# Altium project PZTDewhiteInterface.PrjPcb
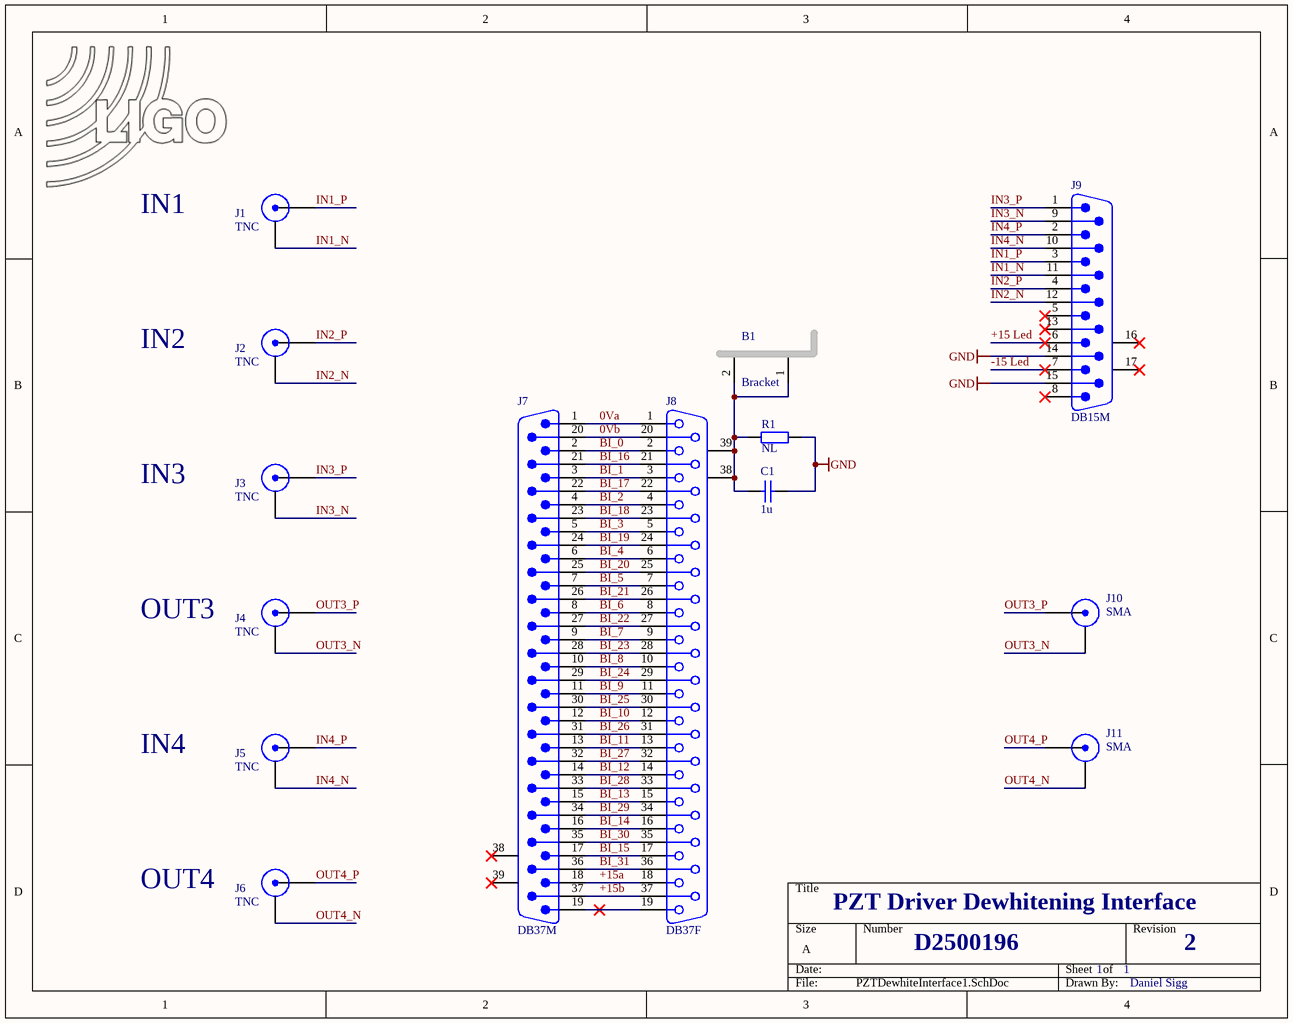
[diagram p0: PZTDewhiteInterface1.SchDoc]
REV: 2; DCC: D2500196
1 sheet, 15 parts. Net scope: global (net labels, ports and power ports of the same name join across sheets).
Board file: PZTDewhiteInterface.PcbDoc

## Sheet PZTDewhiteInterface1.SchDoc
size A; DocumentNumber: D2500196; Revision: 2; SheetNumber: 1; SheetTotal: 1

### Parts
B1  Bracket  [Bracket-RA_708]
C1  1u  [CC2013-0805]
J1  TNC  [TNC2]
J2  TNC  [TNC2]
J3  TNC  [TNC2]
J4  TNC  [TNC2]
J5  TNC  [TNC2]
J6  TNC  [TNC2]
J7  DB37M  [DB37M-RA]
J8  DB37F  [DB37F-RA]
J9  DB15M  [DB15M-RA]
J10  SMA  [SMA]
J11  SMA  [SMA]
LOGO1  LIGO logo  [LIGO_LOGO]  (value not drawn)  (no BOM)
R1  NL  [CR2012-0805]

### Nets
GND: C1.2 J9.14 J9.15 R1.2
0Va: J7.1 J8.1
0Vb: J7.20 J8.20
+15 Led: J9.6
+15a: J7.18 J8.18
+15b: J7.37 J8.37
-15 Led: J9.7
BI_0: J7.2 J8.2
BI_1: J7.3 J8.3
BI_2: J7.4 J8.4
BI_3: J7.5 J8.5
BI_4: J7.6 J8.6
BI_5: J7.7 J8.7
BI_6: J7.8 J8.8
BI_7: J7.9 J8.9
BI_8: J7.10 J8.10
BI_9: J7.11 J8.11
BI_10: J7.12 J8.12
BI_11: J7.13 J8.13
BI_12: J7.14 J8.14
BI_13: J7.15 J8.15
BI_14: J7.16 J8.16
BI_15: J7.17 J8.17
BI_16: J7.21 J8.21
BI_17: J7.22 J8.22
BI_18: J7.23 J8.23
BI_19: J7.24 J8.24
BI_20: J7.25 J8.25
BI_21: J7.26 J8.26
BI_22: J7.27 J8.27
BI_23: J7.28 J8.28
BI_24: J7.29 J8.29
BI_25: J7.30 J8.30
BI_26: J7.31 J8.31
BI_27: J7.32 J8.32
BI_28: J7.33 J8.33
BI_29: J7.34 J8.34
BI_30: J7.35 J8.35
BI_31: J7.36 J8.36
IN1_N: J1.2(Y) J9.11
IN1_P: J1.1(X) J9.3
IN2_N: J2.2(Y) J9.12
IN2_P: J2.1(X) J9.4
IN3_N: J3.2(Y) J9.9
IN3_P: J3.1(X) J9.1
IN4_N: J5.2(Y) J9.10
IN4_P: J5.1(X) J9.2
OUT3_N: J4.2(Y) J10.2(Y)
OUT3_P: J4.1(X) J10.1(X)
OUT4_N: J6.2(Y) J11.2(Y)
OUT4_P: J6.1(X) J11.1(X)
NetB1_1: B1.1(GND) B1.2(GND) C1.1 J8.38 J8.39 R1.1
NetJ7_19: J7.19 J8.19

Not connected (* = marked no-connect by the designer): J7 38* 39*; J9 5* 8* 13* 16(MH1)* 17(MH2)*

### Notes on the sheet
- IN1
- IN2
- IN3
- OUT3
- IN4
- OUT4
- PZT Driver Dewhitening Interface
- Daniel Sigg

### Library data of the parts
B1 = Bracket_708: Keystone Electronics right-angle 6-32 steel, 708; Part Number: 36-708-ND
C1 = ChipCap: Capacitor, surface mount; Part Number: 1276-2928-1-ND; Tolerance: 10%
J1-J6 = BNC: TNC, PCB Mount, Right Angle; Part Number: A32444-ND
J7 = DB37M: Plug Assembly, 37 Position, Right Angle, .318 Series; Part Number: 5747843-2-ND
J8 = DB37F: Receptacle Assembly, 37 Position, Right Angle, .318 Series; Part Number: A32130-ND
J9 = DB15M: Plug Assembly, 15 Position, Right Angle, .318 Series; Part Number: 609-6495-ND
J10 J11 = SMA: SMA, PCB Mount, Straight; Part Number: 900-0732517040-ND
LOGO1 = LIGO_logo
R1 = ChipRes1: Resistor, surface mount; Tolerance: 1%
